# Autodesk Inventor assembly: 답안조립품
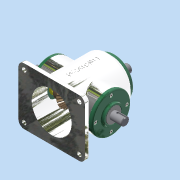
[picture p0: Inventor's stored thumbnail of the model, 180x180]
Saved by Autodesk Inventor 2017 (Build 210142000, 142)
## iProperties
Part Number: 답안조립품
Material: 일반
Document SubType Name: Assembly
Designer: MRC
Author: MRC
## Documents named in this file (16)
- C:\Users\MRC\Desktop\710116V1009\답안조립품.iam
- C:\Users\MRC\Desktop\710116V1009\본체.ipt
- C:\Users\MRC\Desktop\710116V1009\메인 베벨기어.ipt
- C:\Users\MRC\Desktop\710116V1009\메인 축.ipt
- 메인 축.ipt
- C:\Users\MRC\Desktop\710116V1009\베어링 6203.ipt
- C:\Users\MRC\Desktop\710116V1009\볼트 M4.ipt
- 볼트 M4.ipt
- C:\Users\MRC\Desktop\710116V1009\서브 베벨기어.ipt
- C:\Users\MRC\Desktop\710116V1009\서브 축.ipt
- 서브 축.ipt
- C:\Users\MRC\Desktop\710116V1009\오일 실.ipt
- 오일 실.ipt
- C:\Users\MRC\Desktop\710116V1009\커버.ipt
- C:\Users\MRC\Desktop\710116V1009\키 4x4.ipt
- C:\Users\MRC\Desktop\710116V1009\키 5x5.ipt
